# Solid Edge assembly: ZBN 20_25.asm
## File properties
Title: Zylinder
Author: bmolnar
Template: iso metric assembly.asm
Last saved by: bmolnar
Revision: 12
Application: Solid Edge
Username: bmolnar
Dokumentum tartalom típus: 1
Document Number: ZBN 20/25
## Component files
Kit_1.par
Kit_2.par
Profilrohr.par
Kolbenstange.par
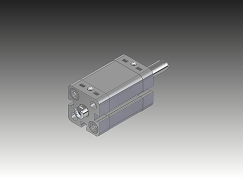
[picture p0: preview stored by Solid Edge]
